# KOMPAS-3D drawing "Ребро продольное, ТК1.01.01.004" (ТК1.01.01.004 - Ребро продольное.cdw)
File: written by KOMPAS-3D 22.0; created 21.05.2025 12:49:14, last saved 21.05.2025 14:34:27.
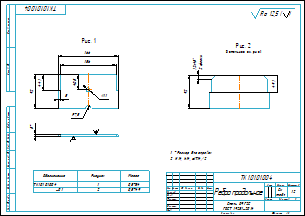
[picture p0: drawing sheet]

Sheet 1: A3, landscape

Document properties: Автор: user; Знак неуказанной шероховатости: 4; Параметр неуказанной шероховатости: Ra 12,5; Масса: 0.575358; Полное имя файла: ..\Ребро продольное.m3d

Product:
- Part/product: Ребро продольное  | designation ТК1.01.01.004
    Масса: 0.575358
    Форматы листов документа: A3
- Part/product: Ребро продольное  | designation ТК1.01.01.004-01
    Масса: 0.574941
    Форматы листов документа: A4
    source file: ..\Ребро продольное _ -01.cdw

Title block, sheet 1: Наименование: Ребро продольное; designation: ТК1.01.01.004; Материал: Сталь 09Г2С / ГОСТ 19281-2014; Масса: 0,58; Количество листов документа: 1; Форматы листов документа: A3; stored path: D:\Рабочая папка\АРХИВ\612\05\Задание №6 - Тележка для крыши\3Д\Тележка в сборе\Корпус тележки\КД\Чертеж Ребро продольное.cdw

Views: Вид 1, Слева, Проекционный вид 2, Вид 3
Referenced files in D:\Рабочая папка\АРХИВ\612\05\Задание №6 - Тележка для крыши\3Д\Тележка в сборе\Корпус тележки\: Ребро продольное.m3d
Referenced files in D:\Работа\2025\5. Май\Задание №6 - Тележка для крыши\3Д\Тележка в сборе\Корпус тележки\: Ребро продольное.m3d
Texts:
  Рис. 1
  Рисунок
  ТК1.01.01.004 - 01
  ТК1.01.01.004-01
  Стиль таблицы исполнений
  Рис. 2
  Остальное см. рис.1
  Ra 12,5
  Ra 12,5 ( )
  BOSimple***Material:4ccf0190-16b6-4223-9222-aa108d28a442
  ТК1.01.01.004-01 Ребро продольное
  ТК1.01.01.004 Ребро продольное
Dimensions and other numbers on the sheet: 166; 156; 11; 44,1; 92; 7,5; 40,5; 5; 7; 1; 0,5754; -01; 2; 0,5749; 12; 2 фаски; 49,1; 1:2; 0,58; 01

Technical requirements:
  *Размер для справок.
  H14, h14, ±IT14/2.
